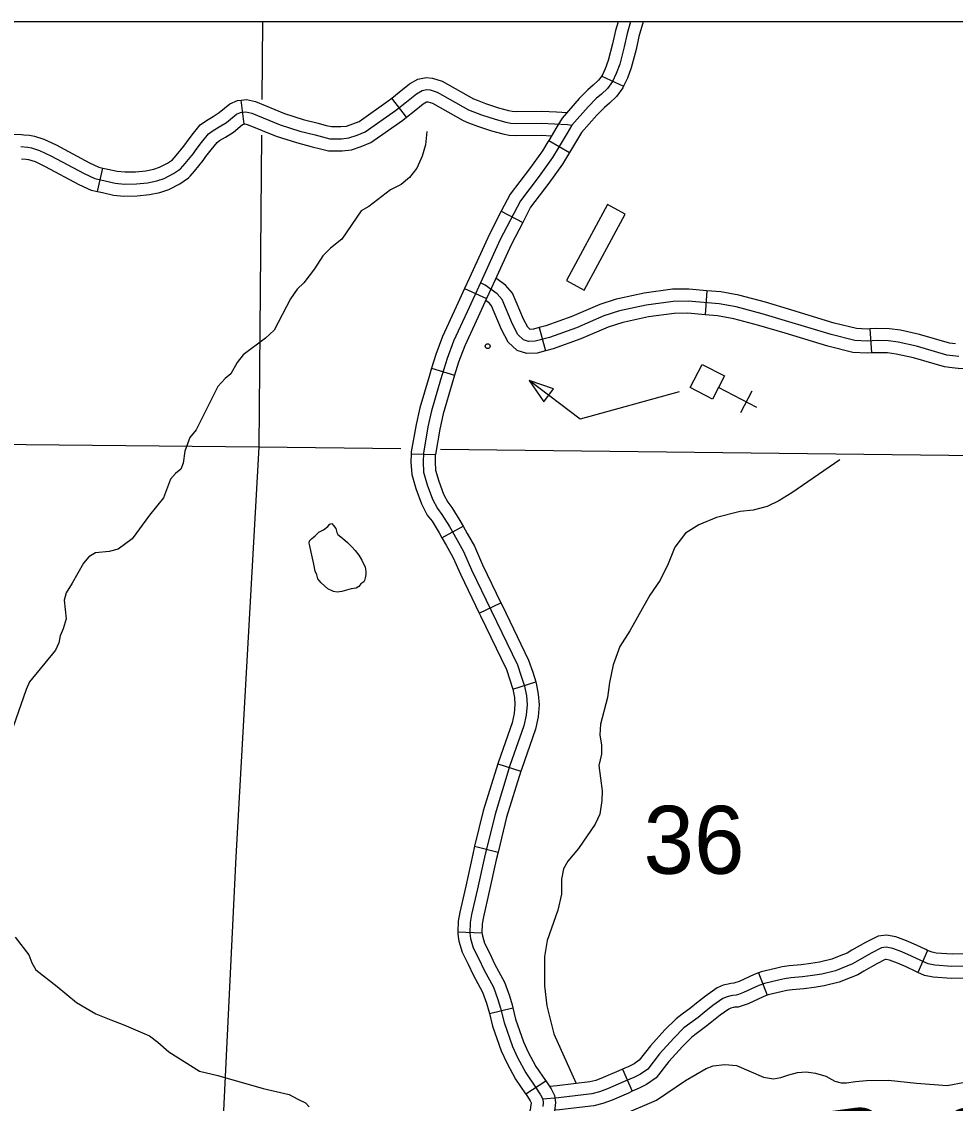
# Model space of a CAD drawing. Extents: x 0 to 3171, y 0 to 2059.
# Drawn here: x 1303.9 to 1400.7, y 1142.5 to 1254.6 of the extents above; entities that cross this region are included whole.
import ezdxf

# ---------------------------------------------------------------- set-up
doc = ezdxf.new("R2010")
doc.units = 0
for name, color, linetype in [('Default', 7, 'Continuous'), ('Level 32', 7, 'Continuous'), ('Level 35', 7, 'Continuous'), ('Level 45', 7, 'Continuous'), ('Level 5', 7, 'Continuous'), ('Level 57', 7, 'Continuous')]:
    doc.layers.add(name, color=color, linetype=linetype)

msp = doc.modelspace()

# ---------------------------------------------------------------- linework, layer by layer
at = {"layer": 'Default'}
msp.add_line((2119.81, 1254.61), (1029.42, 1254.61), dxfattribs=at)
msp.add_lwpolyline([(2119.81, 1254.61), (1029.42, 1254.61), (1029.42, 254.41), (2119.81, 254.41)], close=True, dxfattribs=at)
msp.add_lwpolyline([(2119.81, 1254.61), (1029.42, 1254.61), (1029.42, 254.41), (2119.81, 254.41)], close=True, dxfattribs=at)
msp.add_lwpolyline([(2119.81, 1254.61), (1029.42, 1254.61), (1029.42, 254.41), (2119.81, 254.41)], close=True, dxfattribs=at)
at = {"layer": 'Level 32'}
for p, q in [((1364.05, 1248.96), (1366.32, 1247.91)), ((1358.55, 1242.31), (1360.71, 1241.04)), ((1353.63, 1234.96), (1355.85, 1233.81)), ((1349.83, 1226.96), (1352.11, 1225.92)), ((1346.4, 1218.69), (1348.79, 1217.96)), ((1344.3, 1209.83), (1346.79, 1209.73)), ((1347.48, 1201.11), (1349.67, 1202.33)), ((1351.34, 1193.29), (1353.59, 1194.38)), ((1354.82, 1185.43), (1357.21, 1186.17)), ((1353.27, 1177.67), (1355.66, 1176.94)), ((1350.87, 1169.14), (1353.3, 1168.54)), ((1349.11, 1160.27), (1351.61, 1160.18)), ((1352.4, 1151.81), (1354.82, 1152.4)), ((1356.16, 1143.47), (1358.26, 1144.83))]:
    msp.add_line(p, q, dxfattribs=at)
for points in [[(1367.04, 1254.61), (1366.69, 1253.39), (1366.38, 1252.01), (1365.91, 1250.22), (1365.56, 1249.24), (1365.17, 1248.4), (1364.65, 1247.7), (1364.01, 1247.1), (1363.47, 1246.63), (1362.63, 1245.78), (1360.95, 1243.88), (1360.45, 1243.07), (1359.54, 1241.51)], [(1365.74, 1254.61), (1365.47, 1253.7), (1365.17, 1252.3), (1364.72, 1250.59), (1364.4, 1249.72), (1364.05, 1248.96)], [(1368.34, 1254.61), (1367.9, 1253.09), (1367.6, 1251.72), (1367.11, 1249.84), (1366.71, 1248.77), (1366.32, 1247.91)], [(1364.09, 1249.04), (1363.71, 1248.54), (1363.17, 1248.02), (1362.61, 1247.54), (1361.71, 1246.64), (1359.95, 1244.62), (1359.38, 1243.71), (1358.55, 1242.31)], [(1366.32, 1247.91), (1366.25, 1247.76), (1365.59, 1246.87), (1364.85, 1246.17), (1364.32, 1245.71), (1363.54, 1244.93), (1361.96, 1243.13), (1361.52, 1242.42), (1360.71, 1241.04)], [(1359.54, 1241.51), (1358.94, 1240.54), (1357.56, 1238.61), (1355.61, 1236.05), (1353.52, 1232.03), (1351.47, 1227.53), (1350.1, 1224.54), (1348.69, 1221.5), (1348.01, 1219.71), (1347.34, 1217.48), (1346.39, 1214.28), (1346.02, 1212.62), (1345.55, 1209.89), (1345.52, 1208.98), (1345.58, 1207.9), (1345.95, 1206.61), (1346.49, 1205.13), (1347.02, 1204.14), (1347.48, 1203.53), (1348.26, 1202.28), (1349.01, 1200.95), (1349.73, 1199.68), (1350.56, 1197.79), (1352.59, 1193.58), (1355.31, 1187.94), (1355.71, 1186.78), (1356.03, 1185.74), (1356.23, 1184.73), (1356.3, 1183.81), (1356.21, 1182.72), (1355.97, 1181.61), (1354.53, 1177.5), (1352.98, 1172.48), (1351.89, 1168.02), (1351.17, 1164.73), (1350.56, 1162.06), (1350.4, 1161.25), (1350.36, 1160.12), (1350.45, 1159.59), (1350.73, 1158.63), (1351.32, 1157.47), (1351.82, 1156.38), (1352.83, 1154.55), (1353.28, 1153.26), (1353.55, 1152.36), (1353.92, 1150.86), (1354.79, 1148.39), (1355.31, 1147.25), (1356.17, 1145.66), (1357.19, 1144.17), (1357.71, 1143.36), (1357.93, 1142.93)], [(1358.55, 1242.31), (1358.46, 1242.15), (1357.9, 1241.23), (1356.55, 1239.36), (1354.55, 1236.72), (1353.63, 1234.96)], [(1360.71, 1241.04), (1360.61, 1240.87), (1359.98, 1239.85), (1358.56, 1237.87), (1356.67, 1235.38), (1355.85, 1233.81)], [(1353.63, 1234.96), (1352.4, 1232.57), (1350.33, 1228.05), (1349.83, 1226.96)], [(1355.85, 1233.81), (1354.64, 1231.48), (1352.61, 1227.01), (1352.11, 1225.92)], [(1349.83, 1226.96), (1348.97, 1225.06), (1347.53, 1221.99), (1346.83, 1220.11), (1346.4, 1218.69)], [(1352.11, 1225.92), (1351.24, 1224.01), (1349.84, 1221.01), (1349.2, 1219.31), (1348.79, 1217.96)], [(1346.4, 1218.69), (1346.14, 1217.84), (1345.18, 1214.59), (1344.8, 1212.87), (1344.3, 1210.02), (1344.3, 1209.83)], [(1348.79, 1217.96), (1348.54, 1217.13), (1347.6, 1213.96), (1347.25, 1212.38), (1346.8, 1209.76), (1346.79, 1209.73)], [(1344.3, 1209.83), (1344.26, 1208.96), (1344.34, 1207.68), (1344.77, 1206.23), (1345.35, 1204.62), (1345.96, 1203.47), (1346.45, 1202.82), (1347.19, 1201.64), (1347.48, 1201.11)], [(1346.79, 1209.73), (1346.77, 1208.99), (1346.82, 1208.11), (1347.14, 1207), (1347.64, 1205.64), (1348.08, 1204.81), (1348.51, 1204.24), (1349.34, 1202.92), (1349.67, 1202.33)], [(1349.67, 1202.33), (1350.1, 1201.56), (1350.85, 1200.24), (1351.7, 1198.31), (1353.59, 1194.38)], [(1347.48, 1201.11), (1347.92, 1200.34), (1348.61, 1199.12), (1349.43, 1197.26), (1351.34, 1193.29)], [(1353.59, 1194.38), (1353.72, 1194.12), (1356.47, 1188.42), (1356.9, 1187.17), (1357.21, 1186.17)], [(1351.34, 1193.29), (1351.47, 1193.03), (1354.16, 1187.47), (1354.52, 1186.4), (1354.82, 1185.43)], [(1354.82, 1185.43), (1354.99, 1184.57), (1355.04, 1183.82), (1354.97, 1182.9), (1354.76, 1181.95), (1353.34, 1177.89), (1353.27, 1177.67)], [(1357.21, 1186.17), (1357.25, 1186.04), (1357.47, 1184.9), (1357.55, 1183.81), (1357.45, 1182.54), (1357.17, 1181.27), (1355.72, 1177.11), (1355.66, 1176.94)], [(1353.27, 1177.67), (1351.77, 1172.81), (1350.87, 1169.14)], [(1355.66, 1176.94), (1354.18, 1172.15), (1353.3, 1168.54)], [(1350.87, 1169.14), (1350.67, 1168.31), (1349.95, 1165), (1349.33, 1162.32), (1349.16, 1161.39), (1349.11, 1160.27)], [(1353.3, 1168.54), (1353.11, 1167.74), (1352.39, 1164.45), (1351.78, 1161.81), (1351.65, 1161.11), (1351.61, 1160.18)], [(1349.11, 1160.27), (1349.11, 1160.04), (1349.23, 1159.31), (1349.56, 1158.16), (1350.19, 1156.93), (1350.7, 1155.82), (1351.68, 1154.03), (1352.09, 1152.87), (1352.34, 1152.04), (1352.4, 1151.81)], [(1351.61, 1160.19), (1351.67, 1159.87), (1351.9, 1159.09), (1352.45, 1158.02), (1352.94, 1156.94), (1353.97, 1155.06), (1354.47, 1153.64), (1354.75, 1152.69), (1354.82, 1152.4)], [(1352.4, 1151.81), (1352.72, 1150.5), (1353.63, 1147.92), (1354.19, 1146.7), (1355.1, 1145.01), (1356.15, 1143.48), (1356.16, 1143.47)], [(1354.82, 1152.4), (1355.12, 1151.21), (1355.95, 1148.86), (1356.43, 1147.81), (1357.23, 1146.31), (1358.23, 1144.87), (1358.26, 1144.83)], [(1358.26, 1144.83), (1358.8, 1143.99), (1359.14, 1143.31), (1359.25, 1142.57), (1359.19, 1141.96), (1359.05, 1141.3), (1358.88, 1140.49), (1358.56, 1139.64), (1357.66, 1138.3), (1356.85, 1137.25), (1356.41, 1136.53), (1356.2, 1136.27), (1356.14, 1136.06)], [(1356.16, 1143.47), (1356.63, 1142.74), (1356.73, 1142.55), (1356.73, 1142.51), (1356.71, 1142.33), (1356.61, 1141.81), (1356.47, 1141.2), (1356.32, 1140.78), (1355.63, 1139.76), (1354.79, 1138.67), (1354.37, 1138.08), (1353.94, 1137.44), (1353.74, 1136.74)], [(1357.93, 1142.93), (1357.99, 1142.54), (1357.95, 1142.15)]]:
    msp.add_lwpolyline(points, dxfattribs=at)
at = {"layer": 'Level 35'}
for points in [[(1345.9, 1243.22), (1345.77, 1241.83), (1345.42, 1240.66), (1344.89, 1239.43), (1344.13, 1238.45), (1343.24, 1237.74), (1342.15, 1237.17), (1339.89, 1235.45), (1339.1, 1234.99), (1337.11, 1232.07), (1335.91, 1231.15), (1335.14, 1230.33), (1334.27, 1229), (1333.15, 1227.53), (1332.47, 1226.89), (1331.77, 1225.89), (1330.09, 1222.63), (1329.19, 1221.8), (1326.88, 1220.09), (1326.24, 1219.3), (1325.6, 1218.12), (1325, 1217.62), (1324.23, 1216.81), (1321.99, 1212.3), (1321.35, 1211.51), (1320.81, 1210.1), (1320.66, 1208.84), (1320.4, 1208.22), (1319.86, 1207.78), (1319.35, 1207.19), (1318.62, 1205.27), (1317.16, 1203.46), (1315.35, 1201), (1313.9, 1199.94), (1312.97, 1199.69), (1311.56, 1199.54), (1310.85, 1199.13), (1310.31, 1198.48), (1309.14, 1196.4), (1308.51, 1195.42), (1308.3, 1194.66), (1308.53, 1192.71), (1308.21, 1191.67), (1307.88, 1190.95), (1307.74, 1190.21), (1307.42, 1189.46), (1304.73, 1186.18), (1304.36, 1185.4), (1303.02, 1181.53)], [(1388.75, 1209.21), (1383.75, 1205.79), (1382.4, 1204.94), (1381.19, 1204.35), (1379.75, 1203.98), (1378.4, 1203.84), (1375.96, 1203.23), (1374.12, 1202.45), (1372.72, 1201.58), (1371.63, 1200.13), (1370.94, 1198.42), (1370.11, 1196.72), (1369.02, 1195.16), (1366.96, 1191.48), (1365.92, 1189.86), (1365.22, 1187.93), (1364.85, 1186.1), (1364.66, 1184.56), (1363.93, 1181.81), (1363.85, 1180.68), (1364.02, 1179.63), (1364.03, 1178.69), (1363.75, 1177.52), (1364.09, 1174.87), (1364.07, 1173.89), (1363.86, 1172.48), (1363.36, 1171.42), (1361.65, 1168.91), (1360.54, 1167.59), (1360.09, 1166.81), (1359.87, 1165.73), (1359.88, 1164.16), (1359.5, 1162.52), (1358.4, 1159.38), (1358.1, 1157.7), (1358.11, 1154.68), (1358.34, 1152.61), (1359.08, 1149.7), (1361.38, 1144.54)], [(1334.34, 1197.67), (1334.21, 1198.39), (1334.06, 1199.01), (1333.93, 1199.62), (1333.77, 1200.27), (1333.71, 1200.56), (1333.73, 1200.8), (1333.97, 1201.01), (1334.32, 1201.3), (1334.73, 1201.69), (1335.19, 1201.95), (1335.63, 1202.3), (1335.87, 1202.54), (1336.06, 1202.59), (1336.24, 1202.39), (1336.48, 1202.06), (1336.59, 1201.67), (1336.7, 1201.45), (1337.16, 1201.06), (1337.7, 1200.62), (1338.14, 1200.18), (1338.47, 1199.79), (1338.86, 1199.31), (1339.16, 1198.79)], [(1339.16, 1198.79), (1339.51, 1198.07), (1339.6, 1197.65), (1339.6, 1197.3), (1339.53, 1196.95), (1339.45, 1196.67), (1339.38, 1196.54), (1339.08, 1196.34), (1338.86, 1196.08), (1338.57, 1195.9), (1338.07, 1195.82), (1337.11, 1195.55), (1336.63, 1195.49), (1336.24, 1195.55), (1335.63, 1195.84), (1335.3, 1196.12), (1334.95, 1196.45), (1334.62, 1196.87), (1334.49, 1197.26), (1334.34, 1197.67)], [(1303.22, 1159.71), (1304.65, 1157.88), (1304.94, 1157.07), (1305.37, 1156.34), (1307.58, 1154.62), (1309.57, 1152.93), (1311.58, 1151.78), (1313.15, 1151.15), (1314.49, 1150.64), (1317.14, 1149.48), (1318.01, 1148.85), (1319.16, 1147.82), (1322.35, 1145.84), (1324.25, 1145.37), (1328.94, 1144.03), (1331.63, 1143.4), (1332.54, 1142.92), (1333.32, 1142.53), (1333.71, 1142.14)], [(1356.62, 1136.87), (1357.03, 1136.83), (1358.63, 1136.69), (1360.08, 1137.08), (1362.45, 1138.14), (1363.23, 1138.68), (1363.93, 1139.4), (1366.17, 1141.32), (1369.71, 1142.81), (1372.73, 1144.87), (1374.89, 1146.09), (1375.59, 1146.37), (1376.81, 1146.53), (1378.02, 1146.41), (1380.82, 1145.22), (1381.85, 1145.02), (1382.63, 1145.18), (1383.44, 1145.44), (1384.33, 1145.68), (1385.24, 1145.77)], [(1385.24, 1145.77), (1386.21, 1145.62), (1387.29, 1145.3), (1388.2, 1144.81), (1388.89, 1144.63), (1389.44, 1144.61), (1390.37, 1144.75), (1391.49, 1144.85), (1393.79, 1144.88), (1396.68, 1144.57), (1399.86, 1144.34), (1401.71, 1144.69)]]:
    msp.add_lwpolyline(points, dxfattribs=at)
at = {"layer": 'Level 45'}
for p, q in [((1326.98, 1244), (1326.67, 1246.48)), ((1343.82, 1244.72), (1342.27, 1246.68)), ((1311.76, 1237.01), (1312.33, 1239.44)), ((1374.96, 1226.72), (1374.76, 1224.23)), ((1357.57, 1222.9), (1358.21, 1220.48)), ((1391.86, 1222.76), (1392.02, 1220.27)), ((1397.84, 1158.35), (1396.84, 1156.05)), ((1380.31, 1156.03), (1381.19, 1153.69)), ((1366.19, 1146.02), (1367.21, 1143.74))]:
    msp.add_line(p, q, dxfattribs=at)
for points in [[(1342.27, 1246.68), (1343.04, 1247.29), (1344.12, 1248.15), (1344.98, 1248.65), (1345.83, 1248.84), (1346.51, 1248.77), (1347.5, 1248.46), (1350.76, 1246.61), (1351.14, 1246.47)], [(1323.29, 1243), (1323.74, 1243.34), (1324.38, 1243.71), (1325.13, 1244.17), (1326.16, 1245.03), (1326.59, 1245.21), (1327.13, 1245.28), (1327.76, 1245.13), (1330.71, 1243.93), (1332.75, 1243.27), (1334.34, 1242.87), (1335.87, 1242.48), (1337.05, 1242.48), (1337.83, 1242.56), (1338.68, 1242.84), (1339.51, 1243.18), (1342.66, 1245.39), (1343.81, 1246.31), (1344.83, 1247.12), (1345.43, 1247.47), (1345.91, 1247.57), (1346.26, 1247.54), (1347, 1247.3), (1350.22, 1245.48), (1351.57, 1244.96), (1352.99, 1244.49), (1354.09, 1244.2), (1354.61, 1244.08), (1355.1, 1244.06), (1357.81, 1244.1), (1360.48, 1243.95), (1360.95, 1243.88)], [(1319.49, 1240.26), (1319.91, 1240.73), (1320.72, 1241.71), (1320.98, 1242.1), (1321.58, 1242.87), (1322.42, 1243.91), (1323.06, 1244.38), (1323.74, 1244.78), (1324.39, 1245.18), (1325.5, 1246.1), (1326.27, 1246.43), (1326.67, 1246.48)], [(1326.67, 1246.48), (1327.21, 1246.55), (1328.14, 1246.32), (1331.14, 1245.1), (1333.1, 1244.47), (1334.64, 1244.08), (1335.49, 1243.86)], [(1335.49, 1243.86), (1336.03, 1243.73), (1336.99, 1243.73), (1337.57, 1243.79), (1338.25, 1244.01), (1338.9, 1244.28), (1341.91, 1246.4), (1342.27, 1246.68)], [(1343.82, 1244.72), (1344.59, 1245.33), (1345.54, 1246.08), (1345.89, 1246.29), (1345.98, 1246.31), (1346.01, 1246.31), (1346.5, 1246.15), (1349.69, 1244.35), (1350.23, 1244.14)], [(1351.14, 1246.47), (1352, 1246.13), (1353.35, 1245.68), (1354.38, 1245.41), (1354.77, 1245.33), (1355.11, 1245.31), (1357.84, 1245.35), (1359.36, 1245.26)], [(1334.88, 1241.44), (1335.72, 1241.23), (1337.12, 1241.23), (1338.09, 1241.33), (1339.11, 1241.66), (1340.12, 1242.08), (1343.41, 1244.39), (1343.82, 1244.72)], [(1359.36, 1245.26), (1360.45, 1245.2)], [(1321.37, 1238.6), (1321.81, 1239.11), (1322.72, 1240.21), (1323.01, 1240.64), (1323.54, 1241.32), (1324.16, 1242.09), (1324.43, 1242.29), (1325.02, 1242.64), (1325.86, 1243.15), (1326.81, 1243.95), (1326.92, 1243.99), (1326.98, 1244)], [(1326.98, 1244), (1327.06, 1244.01), (1327.37, 1243.93), (1330.28, 1242.75), (1332.4, 1242.07), (1334.03, 1241.65), (1334.88, 1241.44)], [(1350.23, 1244.14), (1351.15, 1243.78), (1352.63, 1243.29), (1353.79, 1242.98), (1354.45, 1242.84), (1355.08, 1242.81), (1357.78, 1242.85), (1358.83, 1242.79)], [(1295.31, 1239.68), (1295.74, 1239.99), (1297.26, 1240.94), (1298.71, 1242), (1299.39, 1242.37), (1300.37, 1242.7), (1301.27, 1242.8), (1302.06, 1242.85), (1302.89, 1242.94), (1303.87, 1242.92), (1304.12, 1242.89)], [(1303.8, 1241.67), (1304.54, 1241.6), (1304.92, 1241.52), (1305.75, 1241.27), (1306.92, 1240.71), (1310.39, 1238.86), (1311.5, 1238.35), (1312.55, 1238.11), (1313.61, 1237.87), (1314.55, 1237.78), (1315.8, 1237.81), (1316.95, 1237.92), (1317.91, 1238.12), (1318.68, 1238.37), (1319.66, 1238.86), (1320.37, 1239.36), (1320.86, 1239.92), (1321.72, 1240.96), (1322, 1241.37), (1322.56, 1242.1), (1323.29, 1243)], [(1304.12, 1242.89), (1304.73, 1242.84), (1305.23, 1242.73), (1306.2, 1242.44), (1307.48, 1241.83), (1310.95, 1239.98), (1311.91, 1239.54), (1312.33, 1239.44)], [(1303.9, 1240.4), (1304.35, 1240.36), (1304.61, 1240.31), (1305.29, 1240.1), (1306.35, 1239.59), (1309.84, 1237.74), (1311.09, 1237.16), (1311.76, 1237.01)], [(1312.33, 1239.44), (1312.83, 1239.32), (1313.81, 1239.11), (1314.6, 1239.03), (1315.72, 1239.06), (1316.76, 1239.16), (1317.59, 1239.33), (1318.2, 1239.53), (1319.01, 1239.94), (1319.53, 1240.3), (1319.49, 1240.26)], [(1311.76, 1237.01), (1312.28, 1236.89), (1313.41, 1236.64), (1314.5, 1236.52), (1315.88, 1236.56), (1317.14, 1236.69), (1318.23, 1236.91), (1319.15, 1237.21), (1320.3, 1237.79), (1321.2, 1238.42), (1321.37, 1238.6)], [(1357.57, 1222.9), (1356.97, 1222.74), (1356.64, 1222.72), (1356.59, 1222.74), (1356.37, 1222.94), (1355.93, 1223.79), (1354.78, 1226.46), (1354.07, 1227.31), (1353.07, 1228.03)], [(1401.08, 1219.9), (1399.84, 1220.06), (1396.68, 1220.97), (1394.79, 1221.39), (1393.77, 1221.52), (1392.59, 1221.55), (1391.57, 1221.49), (1390.29, 1221.57), (1387.83, 1222.17), (1380.69, 1224.33), (1378, 1225.04), (1376.23, 1225.36), (1373.02, 1225.63), (1371.47, 1225.62), (1368.66, 1225.24), (1365.89, 1224.63), (1364.28, 1224.11), (1361.42, 1222.89), (1358.63, 1221.88), (1357.16, 1221.49), (1356.46, 1221.47), (1355.94, 1221.64), (1355.36, 1222.17), (1354.8, 1223.26), (1353.71, 1225.8), (1353.21, 1226.39), (1351.95, 1227.29), (1351.47, 1227.53)], [(1374.96, 1226.72), (1373.07, 1226.88), (1371.39, 1226.87), (1368.45, 1226.47), (1365.88, 1225.91)], [(1383.77, 1224.7), (1381.03, 1225.53), (1378.27, 1226.26), (1376.39, 1226.6), (1374.96, 1226.72)], [(1358.21, 1220.48), (1357.34, 1220.25), (1356.28, 1220.21), (1355.29, 1220.54), (1354.36, 1221.39), (1353.66, 1222.72), (1352.63, 1225.14), (1352.36, 1225.47), (1352.01, 1225.71)], [(1365.88, 1225.91), (1365.56, 1225.84), (1363.84, 1225.28), (1360.96, 1224.06), (1358.26, 1223.08), (1357.57, 1222.9)], [(1374.76, 1224.23), (1372.97, 1224.38), (1371.56, 1224.37), (1368.88, 1224.01), (1366.42, 1223.47)], [(1391.86, 1222.76), (1391.57, 1222.74), (1390.47, 1222.81), (1388.16, 1223.37), (1383.77, 1224.7)], [(1366.42, 1223.47), (1366.22, 1223.42), (1364.72, 1222.94), (1361.87, 1221.73), (1359.01, 1220.69), (1358.21, 1220.48)], [(1383.05, 1222.31), (1380.35, 1223.12), (1377.73, 1223.81), (1376.06, 1224.12), (1374.76, 1224.23)], [(1392.02, 1220.27), (1391.57, 1220.24), (1390.1, 1220.33), (1387.5, 1220.96), (1383.05, 1222.31)], [(1400.72, 1221.21), (1400.1, 1221.29), (1396.99, 1222.18), (1395.01, 1222.62), (1393.87, 1222.77), (1392.56, 1222.81), (1391.86, 1222.76)], [(1408.47, 1221.28), (1407.6, 1221.08), (1406.99, 1220.82), (1406.43, 1220.48), (1404.91, 1219.64), (1403.77, 1218.8), (1402.41, 1218.63), (1400.99, 1218.65), (1400.39, 1218.73)], [(1400.39, 1218.73), (1399.59, 1218.84), (1396.37, 1219.75), (1394.57, 1220.16), (1393.67, 1220.27), (1392.61, 1220.3), (1392.02, 1220.27)], [(1397.84, 1158.35), (1397.64, 1158.43), (1396.67, 1158.9), (1395.65, 1159.35), (1394.55, 1159.76), (1393.56, 1159.94), (1392.7, 1159.83), (1391.38, 1159.17), (1389.97, 1158.36), (1389.49, 1158.07), (1388.85, 1157.81)], [(1403.59, 1156.76), (1400.35, 1156.69), (1398.57, 1156.81), (1397.91, 1156.95), (1397.12, 1157.3), (1396.15, 1157.76), (1395.18, 1158.19), (1394.22, 1158.55), (1393.53, 1158.67), (1393.07, 1158.61), (1391.97, 1158.07), (1390.6, 1157.28), (1390.05, 1156.95), (1388.29, 1156.23), (1386.86, 1155.88), (1385.91, 1155.74), (1384.87, 1155.61), (1383.64, 1155.51), (1383.01, 1155.41), (1382.36, 1155.26), (1380.93, 1154.93), (1380.32, 1154.7), (1378.76, 1153.98), (1378.24, 1153.79), (1377.97, 1153.72), (1377.64, 1153.68), (1377.43, 1153.64), (1377.04, 1153.54), (1376.6, 1153.36), (1375.56, 1152.62), (1374.67, 1151.9), (1374.06, 1151.4), (1372.57, 1150.32), (1371.51, 1149.26), (1370.05, 1147.64), (1368.81, 1146.05), (1368.06, 1145.53), (1367.38, 1145.19), (1366.31, 1144.71), (1364.66, 1144), (1363.8, 1143.67), (1363.02, 1143.48), (1359.55, 1143.06), (1357.93, 1142.93)], [(1406.06, 1158.04), (1403.57, 1158.01), (1400.38, 1157.94), (1398.74, 1158.05), (1398.3, 1158.15), (1397.84, 1158.35)], [(1388.85, 1157.81), (1387.91, 1157.43), (1386.62, 1157.11), (1385.74, 1156.98), (1384.74, 1156.85), (1383.49, 1156.75), (1382.77, 1156.64), (1382.08, 1156.47), (1380.57, 1156.13), (1380.31, 1156.03)], [(1396.84, 1156.05), (1396.6, 1156.16), (1395.63, 1156.63), (1394.71, 1157.03), (1393.88, 1157.34), (1393.5, 1157.41), (1393.44, 1157.4), (1392.56, 1156.96), (1391.23, 1156.2), (1390.61, 1155.83), (1389.8, 1155.5)], [(1380.31, 1156.03), (1379.84, 1155.85), (1378.29, 1155.14), (1377.86, 1154.98), (1377.73, 1154.95), (1377.45, 1154.92), (1377.15, 1154.86), (1376.64, 1154.73), (1376, 1154.46), (1374.8, 1153.62), (1373.88, 1152.87), (1373.29, 1152.39), (1372.39, 1151.73)], [(1406.09, 1155.54), (1403.61, 1155.51), (1400.32, 1155.44), (1398.4, 1155.57), (1397.53, 1155.75), (1396.84, 1156.05)], [(1389.8, 1155.5), (1388.68, 1155.04), (1387.1, 1154.66), (1386.08, 1154.5), (1385, 1154.37), (1383.79, 1154.27), (1383.25, 1154.18), (1382.65, 1154.04), (1381.29, 1153.73), (1381.19, 1153.69)], [(1381.19, 1153.69), (1380.8, 1153.55), (1379.23, 1152.82), (1378.62, 1152.6), (1378.2, 1152.48), (1377.83, 1152.45), (1377.71, 1152.42), (1377.44, 1152.35), (1377.21, 1152.26), (1376.31, 1151.63), (1375.46, 1150.94), (1374.82, 1150.41), (1373.85, 1149.71)], [(1372.39, 1151.73), (1371.75, 1151.27), (1370.6, 1150.12), (1369.09, 1148.45), (1367.94, 1146.97), (1367.42, 1146.6), (1366.85, 1146.32), (1366.19, 1146.02)], [(1373.85, 1149.71), (1373.38, 1149.37), (1372.41, 1148.4), (1371.01, 1146.84), (1369.68, 1145.13), (1368.7, 1144.45), (1367.92, 1144.06), (1367.21, 1143.74)], [(1366.19, 1146.02), (1365.81, 1145.85), (1364.18, 1145.16), (1363.43, 1144.87), (1362.8, 1144.72), (1359.42, 1144.3), (1358.67, 1144.24)], [(1367.21, 1143.74), (1366.82, 1143.56), (1365.13, 1142.84), (1364.17, 1142.47), (1363.24, 1142.25), (1359.67, 1141.81), (1359.16, 1141.77)]]:
    msp.add_lwpolyline(points, dxfattribs=at)
at = {"layer": 'Level 5'}
for points in [[(1328.87, 1254.61), (1328.8, 1246.56)], [(1328.77, 1242.84), (1328.48, 1210.5)], [(1328.48, 1210.5), (1269.84, 1211.09), (1239.12, 1211.6)], [(1328.48, 1210.5), (1326.1, 1168.05), (1324.59, 1136.74)], [(1343.23, 1210.32), (1328.48, 1210.5)], [(1414.64, 1209.46), (1347.33, 1210.27)]]:
    msp.add_lwpolyline(points, dxfattribs=at)
at = {"layer": 'Level 57'}
for p, q in [((1364.66, 1235.66), (1360.38, 1227.79)), ((1366.49, 1234.67), (1364.66, 1235.66)), ((1362.21, 1226.79), (1366.49, 1234.67)), ((1360.38, 1227.79), (1362.21, 1226.79)), ((1380.13, 1214.61), (1376.15, 1216.69)), ((1379.6, 1216.3), (1378.45, 1214.08))]:
    msp.add_line(p, q, dxfattribs=at)
for points in [[(1374.47, 1219.09), (1376.78, 1217.89), (1375.53, 1215.49), (1373.23, 1216.69)], [(1358.03, 1215.19), (1359.06, 1216.54), (1356.51, 1217.41)]]:
    msp.add_lwpolyline(points, close=True, dxfattribs=at)
msp.add_lwpolyline([(1372.08, 1216.23), (1361.8, 1213.41), (1356.51, 1217.41)], dxfattribs=at)
msp.add_circle((1352.22, 1220.98), 0.25, dxfattribs=at)

# ---------------------------------------------------------------- texts
at = {"layer": 'Level 35'}
msp.add_text('Panther', height=7.04, rotation=7.7348, dxfattribs=at).set_placement((1387.82, 1134.59))
at = {"layer": 'Level 5'}
msp.add_text('36', height=7.04, dxfattribs=at).set_placement((1368.38, 1166.29))

doc.saveas('drawing.dxf')
